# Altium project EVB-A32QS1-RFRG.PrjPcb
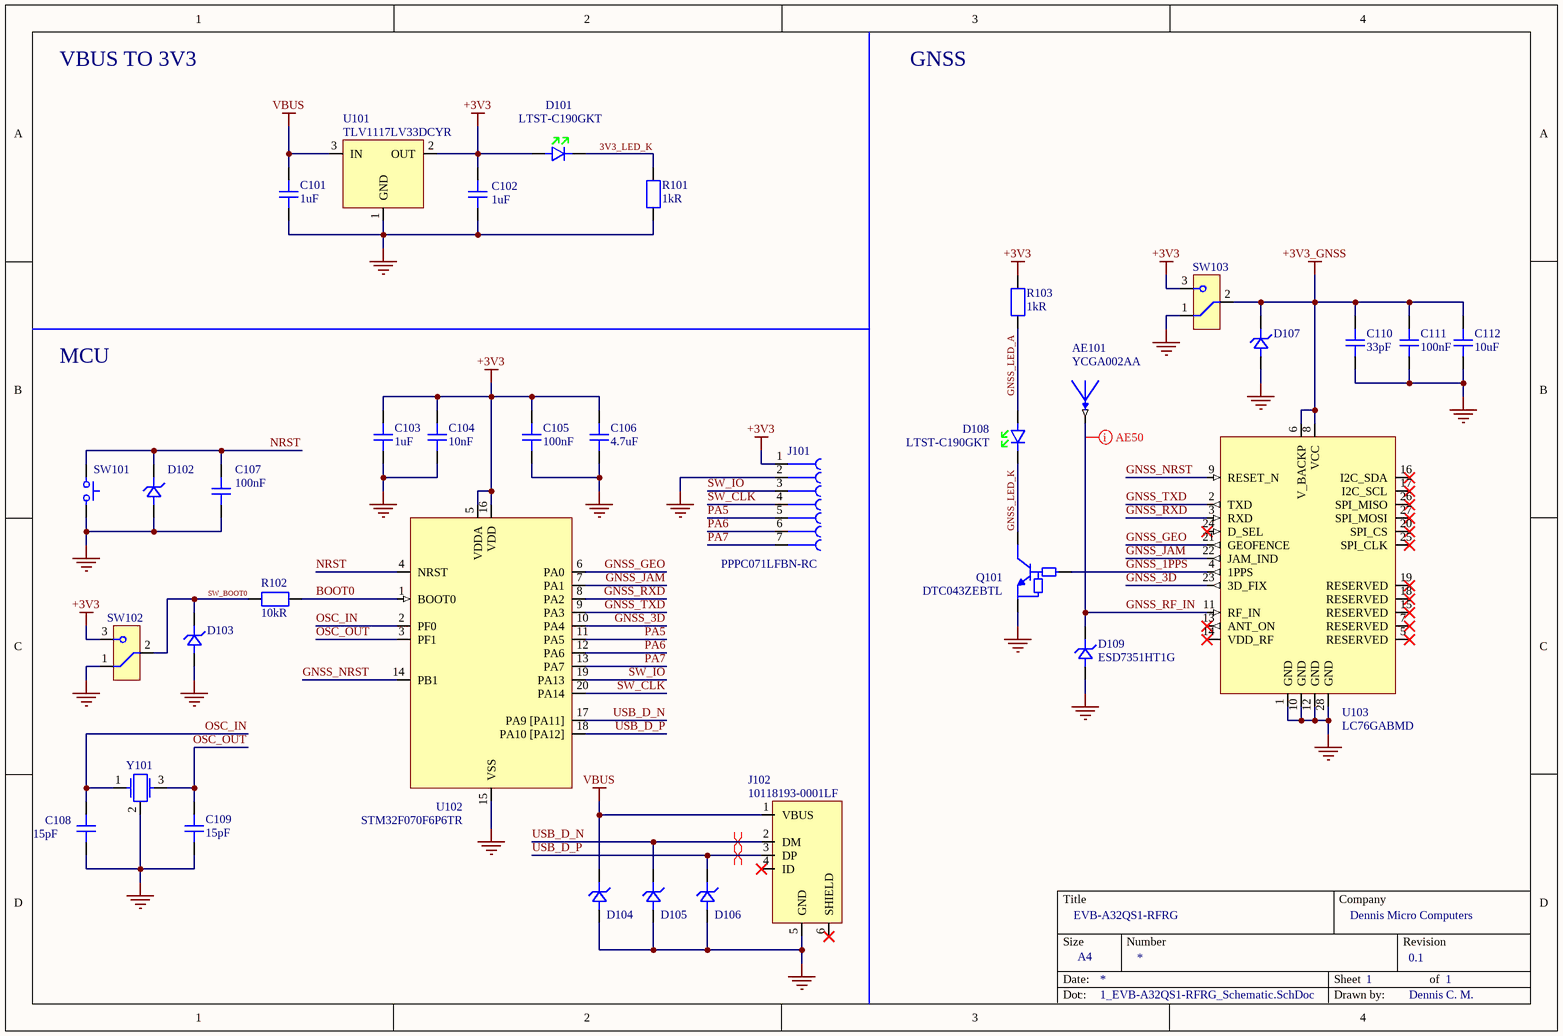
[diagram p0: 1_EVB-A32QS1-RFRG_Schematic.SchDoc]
CompanyName: Dennis Micro Computers; DrawnBy: Dennis C. M.; Revision: 0.1; Title: EVB-A32QS1-RFRG
1 sheet, 35 parts. Net scope: global (net labels, ports and power ports of the same name join across sheets).
Board file: EVB-A32QS1-RFRG_PCB.PcbDoc

## Sheet 1_EVB-A32QS1-RFRG_Schematic.SchDoc: EVB-A32QS1-RFRG
size A4; Author: Dennis C. M; CompanyName: Dennis Micro Computers; DrawnBy: Dennis C. M.; SheetNumber: 1; SheetTotal: 1; Size: A4

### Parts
AE101  YCGA002AA  [AE_Quectel_YCGA002AA]
C101  value 1uF  [C_Yageo_CC_0402_A]  (hidden comment: CC0402MRX5R6BB105)
C102  value 1uF  [C_Yageo_CC_0402_A]  (hidden comment: CC0402MRX5R6BB105)
C103  value 1uF  [C_Yageo_CC_0402_A]  (hidden comment: CC0402MRX5R6BB105)
C104  value 10nF  [C_Yageo_CC_0402_A]  (hidden comment: CC0402KRX7R7BB103)
C105  value 100nF  [C_Samsung_CL_0402_A]  (hidden comment: CL05B104KP5NNNC)
C106  value 4.7uF  [C_Samsung_CL_0402_A]  (hidden comment: CL05A475MP5NRNC)
C107  value 100nF  [C_Samsung_CL_0402_A]  (hidden comment: CL05B104KP5NNNC)
C108  value 15pF  [C_Yageo_CC_0402_A]  (hidden comment: CC0402JRNPO9BN150)
C109  value 15pF  [C_Yageo_CC_0402_A]  (hidden comment: CC0402JRNPO9BN150)
C110  value 33pF  [C_Samsung_CL_0402_A]  (hidden comment: CL05C330JB5NNNC)
C111  value 100nF  [C_Samsung_CL_0402_A]  (hidden comment: CL05B104KP5NNNC)
C112  value 10uF  [C_Samsung_CL_0805_A]  (hidden comment: CL21A106KOQNNNE)
D101  LTST-C190GKT  [D_LED_Lite-On_Green_0603_A]
D102  D5V0F1U2S9-7  [D_TVS_Uni_Diodes_SOD-923_B]  (value not drawn)
D103  D5V0F1U2S9-7  [D_TVS_Uni_Diodes_SOD-923_B]  (value not drawn)
D104  D5V0F1U2S9-7  [D_TVS_Uni_Diodes_SOD-923_B]  (value not drawn)
D105  D5V0F1U2S9-7  [D_TVS_Uni_Diodes_SOD-923_B]  (value not drawn)
D106  D5V0F1U2S9-7  [D_TVS_Uni_Diodes_SOD-923_B]  (value not drawn)
D107  D5V0F1U2S9-7  [D_TVS_Uni_Diodes_SOD-923_B]  (value not drawn)
D108  LTST-C190GKT  [D_LED_Lite-On_Green_0603_A]
D109  ESD7351HT1G  [D_TVS_Uni_Onsemi_SOD-323]
J101  PPPC071LFBN-RC  [J_Sullins_01x07_Socket_2.54mm]
J102  10118193-0001LF  [J_USB_Micro-B_Amphenol_10118193-0001LF]
Q101  DTC043ZEBTL  [Q_Rohm_SOT-416FL_B]
R101  value 1kR  [R_Yageo_RCL_0402_A]  (hidden comment: RC0402FR-071KL)
R102  value 10kR  [R_Yageo_RCL_0402_A]  (hidden comment: RC0402FR-0710KL)
R103  value 1kR  [R_Yageo_RCL_0402_A]  (hidden comment: RC0402FR-071KL)
SW101  PTS647SN50SMTR2LFS  [SW_Tactitle_SPST_C&K_PTS647SN50SMTR2LFS]  (value not drawn)
SW102  JS102011JCQN  [SW_Slide_C&K_JS102011JCQN]  (value not drawn)
SW103  JS102011JCQN  [SW_Slide_C&K_JS102011JCQN]  (value not drawn)
U101  TLV1117LV33DCYR  [U_TI_SOT-223_B]
U102  STM32F070F6P6TR  [U_ST_TSSOP20_B]
U103  LC76GABMD  [U_QUECTEL_LC76G]
Y101  ECS-240-12-37B-CKY-TR  [Y_Crystal_GND24_ECS_240-12-37B-CKY-TR]  (value not drawn)

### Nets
+3V3: C102.2 C103.2 C104.2 C105.2 C106.2 D101.2 J101.1 R103.2 SW102.3 SW103.3 U101.2(OUT) U102.5(VDDA) U102.16(VDD)
+3V3_GNSS: C110.2 C111.2 C112.2 D107.1 SW103.2 U103.6(V_BACKP) U103.8(VCC)
GND: C101.1 C102.1 C103.1 C104.1 C105.1 C106.1 C107.1 C108.1 C109.1 C110.1 C111.1 C112.1 D102.2 D103.2 D104.2 D105.2 D106.2 D107.2 D109.2 J101.2 J102.5(GND) Q101.2(EMITTER) R101.1 SW101.2 SW102.1 SW103.1 U101.1(GND) U102.15(VSS) U103.1(GND) U103.10(GND) U103.12(GND) U103.28(GND) Y101.2
VBUS: C101.2 D104.1 J102.1(VBUS) U101.3(IN)
3V3_LED_K: D101.1 R101.2
BOOT0: R102.2 U102.1(BOOT0)
GNSS_1PPS: Q101.1(BASE) U103.4(1PPS)
GNSS_3D: U102.10(PA4) U103.23(3D_FIX)
GNSS_GEO: U102.6(PA0) U103.21(GEOFENCE)
GNSS_JAM: U102.7(PA1) U103.22(JAM_IND)
GNSS_LED_A: D108.2 R103.1
GNSS_LED_K: D108.1 Q101.3(COLLECTOR)
GNSS_NRST: U102.14(PB1) U103.9(RESET_N)
GNSS_RF_IN: AE101.1 D109.1 U103.11(RF_IN)
GNSS_RXD: U102.8(PA2) U103.3(RXD)
GNSS_TXD: U102.9(PA3) U103.2(TXD)
NRST: C107.2 D102.1 SW101.1 U102.4(NRST)
OSC_IN: C108.2 U102.2(PF0) Y101.1
OSC_OUT: C109.2 U102.3(PF1) Y101.3
PA5: J101.5 U102.11(PA5)
PA6: J101.6 U102.12(PA6)
PA7: J101.7 U102.13(PA7)
SW_BOOT0: D103.1 R102.1 SW102.2
SW_CLK: J101.4 U102.20(PA14)
SW_IO: J101.3 U102.19(PA13)
USB_D_N: D105.1 J102.2(DM) U102.17(PA9_[PA11])
USB_D_P: D106.1 J102.3(DP) U102.18(PA10_[PA12])

Not connected (* = marked no-connect by the designer): J102 4(ID)* 6(SHIELD)*; U103 5(RESERVED)* 7(RESERVED)* 13(ANT_ON)* 14(VDD_RF)* 15(RESERVED)* 16(I2C_SDA)* 17(I2C_SCL)* 18(RESERVED)* 19(RESERVED)* 20(SPI_CS)* 24(D_SEL)* 25(SPI_CLK)* 26(SPI_MISO)* 27(SPI_MOSI)*

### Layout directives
differential pair; differential pair class DIFF_USB: USB_D_N, USB_D_P
net class AE50: GNSS_RF_IN

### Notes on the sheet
- VBUS TO 3V3
- GNSS
- MCU

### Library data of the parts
AE101 = CMP-00025-00001-2: Antenna Module Linear 1602MHz; Manufacturer: Quectel; Frequency Range: 1.559GHz ~ 1.606GHz; Antenna Type: Ceramic Patch; Frequency (Center/Band): 1.5825GHz; Frequency Group: UHF (1GHz ~ 2GHz); RF Family/Standard: Navigation; Number of Bands: 1
C101-C103 = CMP-001-00016-11: Multilayer Ceramic Capacitor, 1 uF, 50 V, ± 10%, X5R, 0402 [1005 Metric]; Voltage Rating (DC): 10V; Tolerance: 20%; Temperature Coefficient: 30ppm/°C
C104 = CMP-001-00029-1: Multilayer Ceramic Capacitor, 0.01 uF, 16 V, ± 10%, X7R, 0402 [1005 Metric]; Dissipation Factor: 3.5%; Voltage Rating: 16V; Temperature Coefficient: 30ppm/°C; Insulation Resistance: 10GR
C105 C107 C111 = CMP-001-00023-3: Multilayer Ceramic Capacitor, 0.1 uF, 10 V, ± 10%, X7R, 0402 [1005 Metric]; Voltage Rating (DC): 10V
C106 = CMP-001-00024-3: Multilayer Ceramic Capacitor, 4.7 uF, 10 V, ± 20%, X5R, 0402 [1005 Metric]; Voltage Rating: 10V
C108 C109 = CMP-001-00017-14: Multilayer Ceramic Capacitor, 15 pF, 10 V, ± 5%, X7R, 0402 [1005 Metric]; Temperature Coefficient: 30ppm/°C; Voltage Rating (DC): 50V; Dielectric: C0G; Insulation Resistance: 100GR
C110 = CMP-001-00030-2: Multilayer Ceramic Capacitor, 33 pF, 50 V, ± 5%, C0G (NP0), 0402 [1005 Metric]; Voltage: 50V; Temperature Coefficient: 300ppm/°C
C112 = CMP-001-00022-4: Multilayer Ceramic Capacitor, 10 uF, 16 V, ± 10%, X5R, 0805 [2012 Metric]; Dielectric: X7R; Voltage: 16V
D101 D108 = CMP-007-00001-3: LED Uni-Color Green 565nm 2-Pin Chip LED T/R; Dominant Wavelength: 569nm; Forward Current: 30mA; Reverse Voltage: 5V; Lens Transparency: Clear; Power Dissipation: 100mW; Number of Elements: 1; Viewing Angle: 130°; Test Current: 10mA; Forward Voltage: 2.1V; Lens Color: Colorless; Voltage: 2V; Lens Size: 0.8mm; Lens Style: Flat,Diffused,Colorless,Rectangular,Clear; Luminous Intensity: 6mcd
D102-D107 = CMP-004-00007-2: Diode TVS Dual Uni-Dir 5.5V 250000W 2-Pin SOD-923 T/R; Max Reverse Leakage Current: 100nA; Number of Unidirectional Channels: 1; ESD Protection: Yes; Diode Type: ZENER; Max Surge Current: 1.5A; Min Breakdown Voltage: 6V; Polarity: Unidirectional; Value: 5E-13F; Max Power Dissipation: 250mW; Clamping Voltage: 10V; Peak Pulse Power: 250kW
D109 = CMP-004-00006-1: TVSDIODE3.3VWMSOD-323; Diode Type: ZENER; Min Breakdown Voltage: 5V; Power Line Protection: No; Number of Unidirectional Channels: 1; Reverse Standoff Voltage: 3.3V
J101 = CMP-002-00007-1: Conn Hdr 7POS 0.1 Gold Pcb; Connector Type: Header; Voltage Rating: 250V; Number of Positions: 7
J102 = CMP-002-00002-12: Usb Connector, 5 Contact(S), Female, Right Angle, Surface Mount Terminal, Locking, Receptacle; Max Voltage Rating (AC): 100V; USB Standard: USB 2.0; Connector Type: USB,Receptacle; Number of Contacts: 5; Number of Ports: 1; Insulation Resistance: 1GR; Pitch: 650um; Current Rating: 1.8A
Q101 = CMP-013-00001-2: TRANS PREBIAS NPN 50V EMT3F; Transition Frequency: 250MHz; Collector-emitter Voltage-Max: 150mV; Continuous Collector Current: 100mA; Output Voltage: 50mV; Max Power Dissipation: 150mW
R101 R103 = CMP-009-00002-11: SMD Chip Resistor, 1 kOhm, ± 1%, 62.5 mW, 0402 [1005 Metric], Thick Film, General Purpose; Max Power Dissipation: 63mW; Temperature Coefficient: 100ppm/°C; Voltage Rating (AC): 50V; Power Rating: 62.5mW
R102 = CMP-009-00003-11: SMD Chip Resistor, 10 kOhm, ± 1%, 62.5 mW, 0402 [1005 Metric], Thick Film, General Purpose; Voltage Rating (DC): 50V; Temperature Coefficient: 100ppm/°C; Power Rating: 62.5mW; Max Power Dissipation: 63mW
SW101 = CMP-011-00000-13: Switch Tactile N.O. SPST Round Button Gull Wing 0.05A 12VDC 100000Cycles 0.98N SMD T/R; pin to pad: 1>1+2 2>3+4; Number of Positions: 2; Operating Force: 100gf; Actuator Type: Standard; Illumination Type: Non-Illuminated; Switch Function: Off-Mom; Switch Travel: 0.25mm; Ratings: IP40
SW102 SW103 = CMP-011-00001-10: JS Series Sub-Miniature Slide Switch SPDT On-On Top Slide 0.3A 6VDC J-Lead Surface Mount T/R; Actuator Type: Standard; Switch Travel: 2mm; Actuator Material: Nylon,Polyamide,PA46; Voltage Rating (DC): 6V; Electrical Life: 5000Cycles
U101 = CMP-019-00002-2: LDO Regulator Pos 3.3V 1A 4-Pin(3+Tab) SOT-223 T/R; pin to pad: 2>2+4; Output Type: Fixed; Power Supply Rejection Ratio (PSRR): 75dB; Polarity: Positive; Dropout Voltage: 570mV; Quiescent Current: 50uA; Max Supply Voltage: 5.5V; Accuracy: 2%; Number of Regulators: 1; Min Input Voltage: 2V
U102 = CMP-020-00001-5: IC MCU 32BIT 32KB FLASH 20TSSOP; Core Architecture: ARM; Oscillator Type: Internal; Number of I/Os: 15; Peripherals: POR,PWM,WDT,DMA; Interface: I2C,SPI,USB,UART,USART
U103 = CMP-00025-00000-4: Navigation BeiDou, Galileo, GLONASS, GPS, GNSS Transceiver Module 1.561GHz, 1.575GHz, 1.602GHz Antenna Not Included Surface Mount; Serial Interfaces: I2C, UART; Sensivity: -166dBm; Supply Voltage: 2.55V ~ 3.6V
Y101 = CMP-003-00000-11: Crystal 24MHz ±10ppm (Tol) ±10ppm (Stability) 12pF FUND 50Ohm 4-Pin Mini-CSMD T/R; pin to pad: 2>2+4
